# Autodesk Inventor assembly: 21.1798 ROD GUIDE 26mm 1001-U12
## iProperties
Created: 2007-03
Part Number: 21.1798 ROD GUIDE 26mm 1001-U12
Document SubType Name: Assembly
Designer: Andy Moles
Translation Standard: STEP AP214IS
File Name: 1001-U12_ASM
Preprocessor: PRO/ENGINEER BY PARAMETRIC TECHNOLOGY CORPORATION, 2005110
Postprocessor: Build: 344b, Release: 11 SP2 - Date: Fri 08/18/2006
Sent Units: MILLIMETERS
Uncertainty: 0.005488572171208001
Author: Andy Moles
